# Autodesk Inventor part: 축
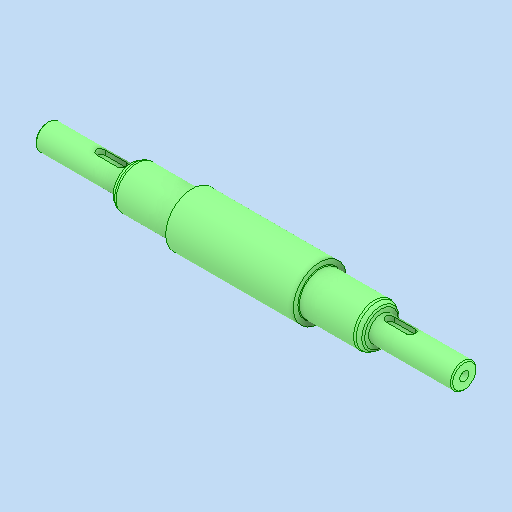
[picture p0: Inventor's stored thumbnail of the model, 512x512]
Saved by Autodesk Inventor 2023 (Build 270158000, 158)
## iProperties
Created: 2026-06
Part Number: 축
Material: 강철, 탄소
Document SubType Name: Modeling
Designer: home
Density: 7.85 g/cm^3
Appearance: 기본값
Author: jhkim
Sending System: Autodesk Inventor 2027
Preprocessor: ST-DEVELOPER v20.1
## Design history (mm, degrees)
feature "솔리드1"
node "솔리드2"
